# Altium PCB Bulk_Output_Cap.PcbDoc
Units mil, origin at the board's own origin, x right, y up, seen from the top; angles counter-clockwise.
Board outline 845 x 1377.95 mil, 6 copper layers (Top Layer, Layer 2, Layer 3, Layer 4, Layer 5, Bottom Layer), stack 43.736 mil thick; 2 components, 2 nets, 4 pads, 63 vias.
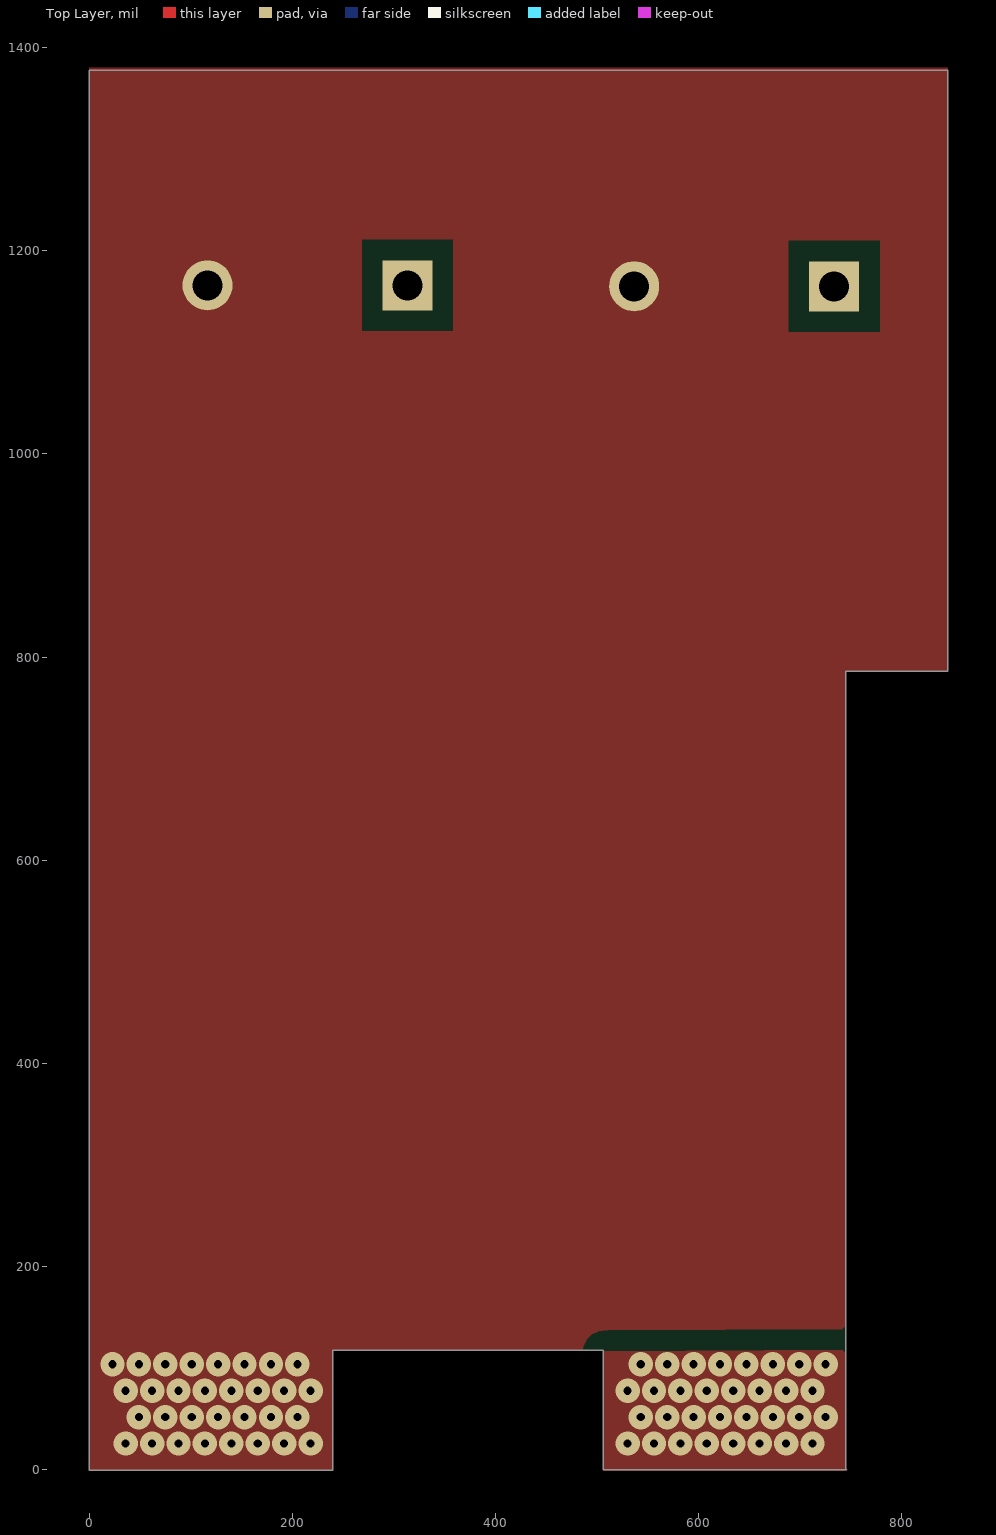
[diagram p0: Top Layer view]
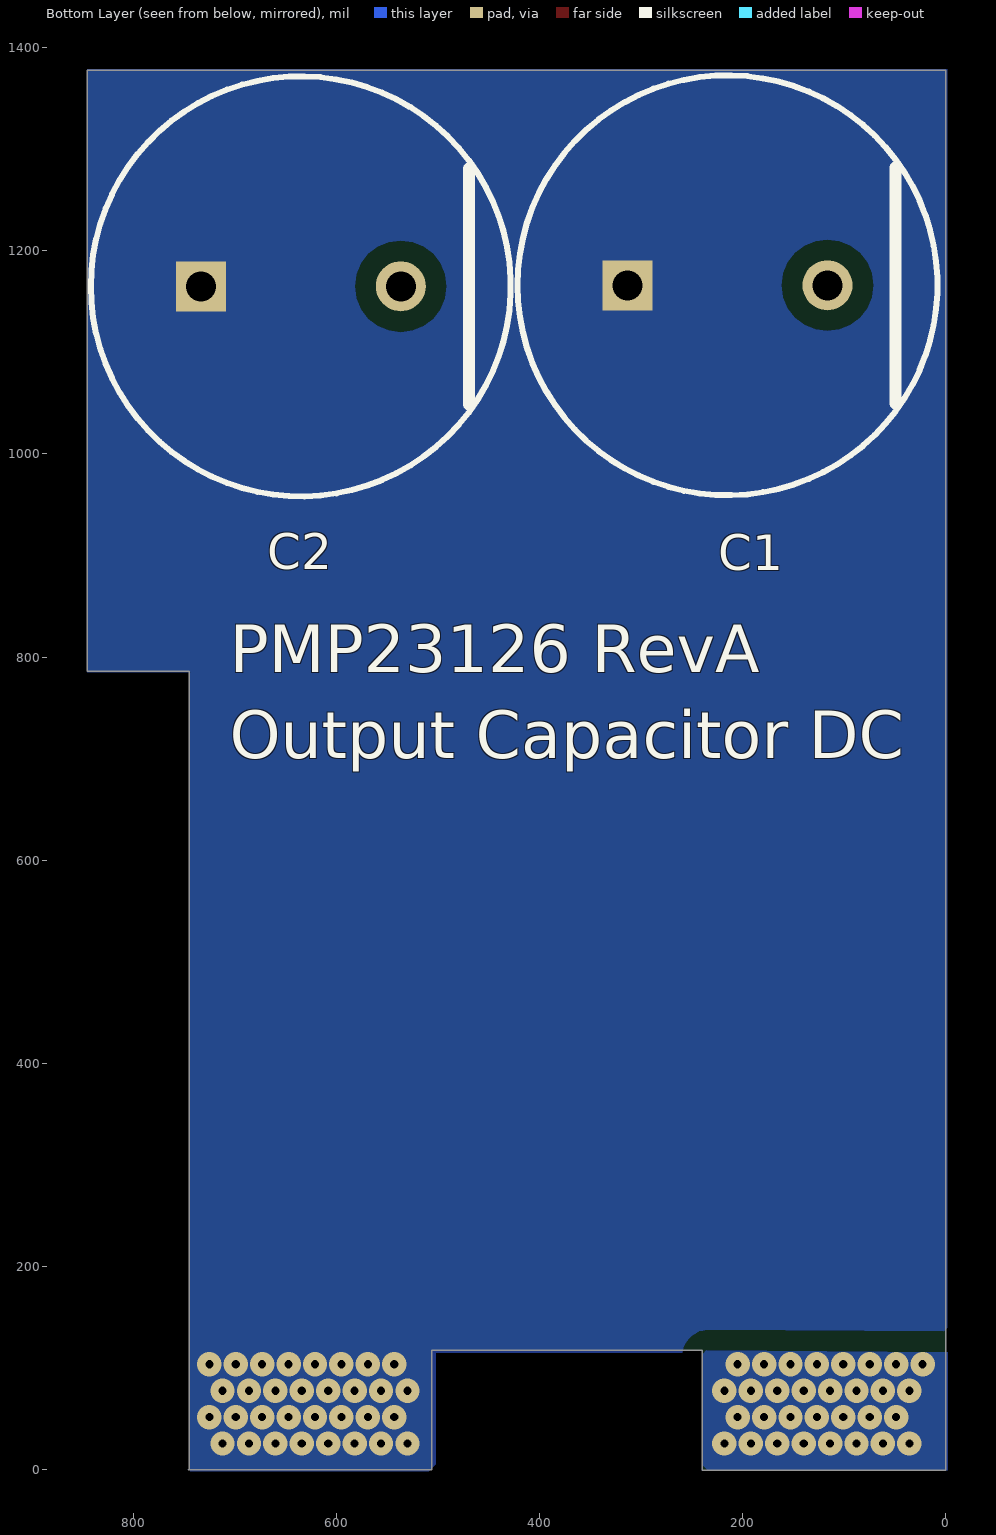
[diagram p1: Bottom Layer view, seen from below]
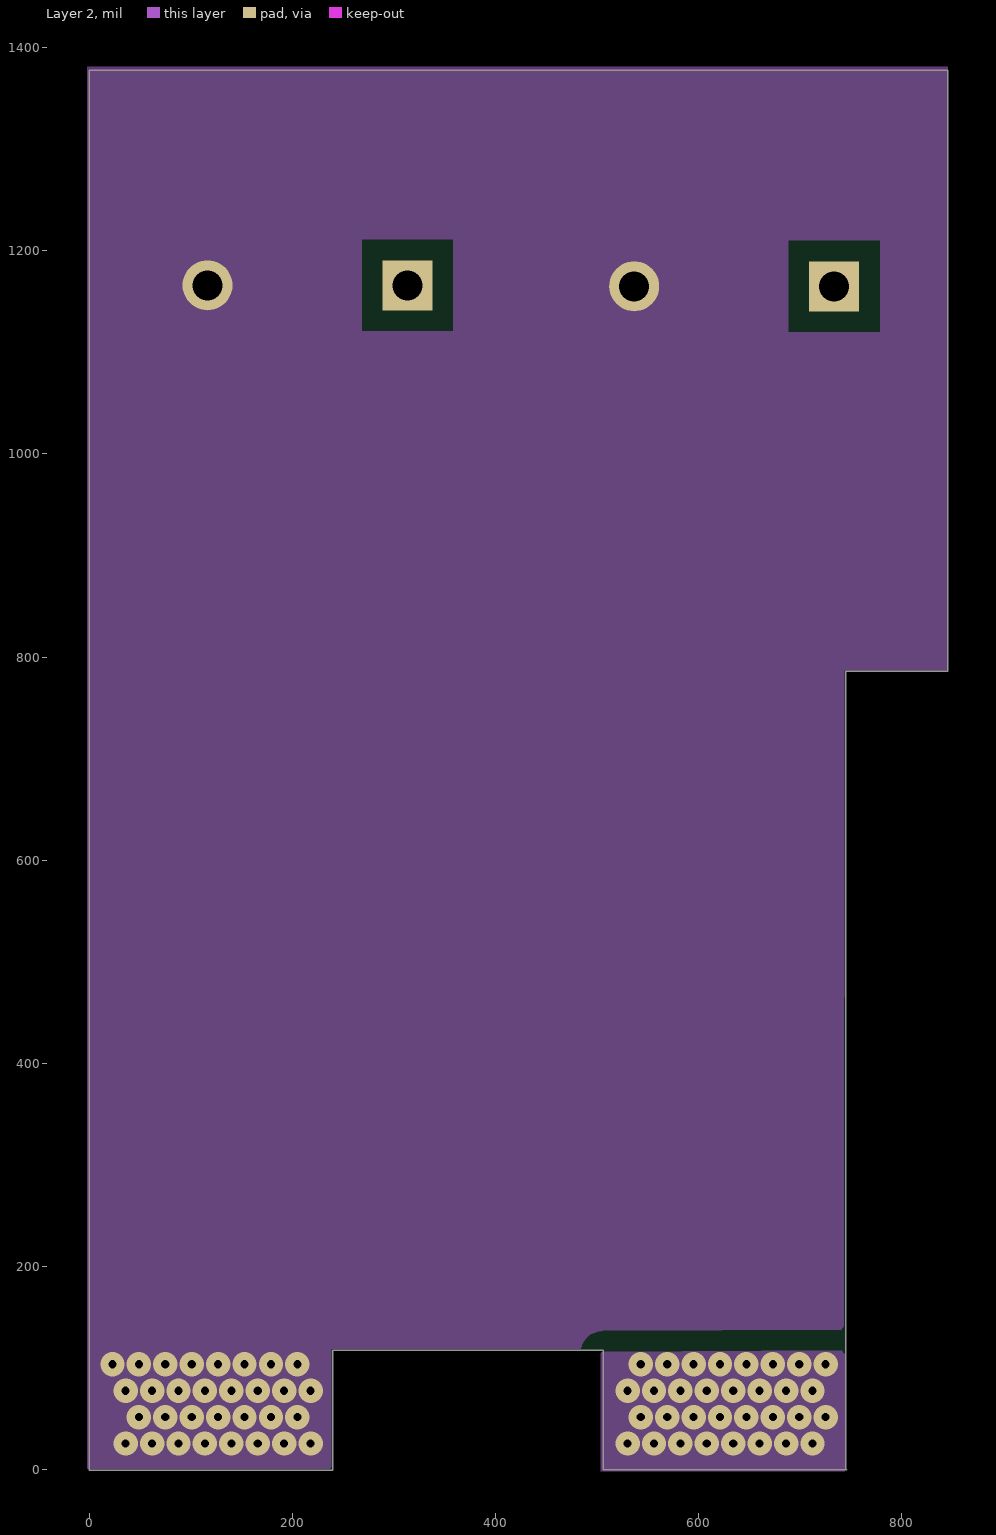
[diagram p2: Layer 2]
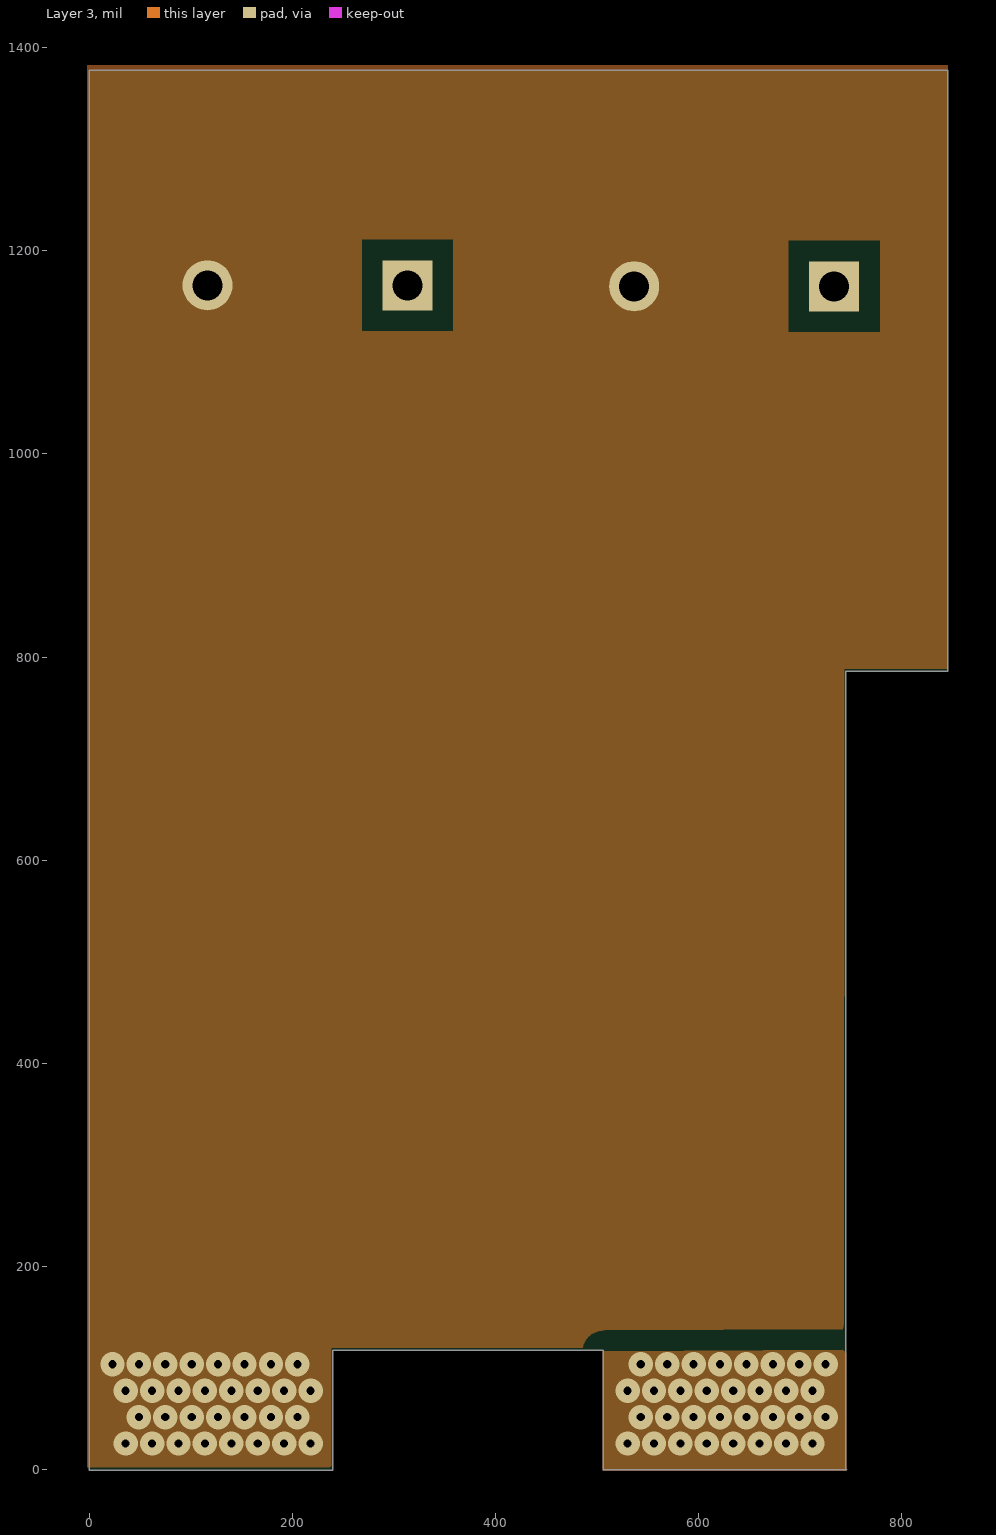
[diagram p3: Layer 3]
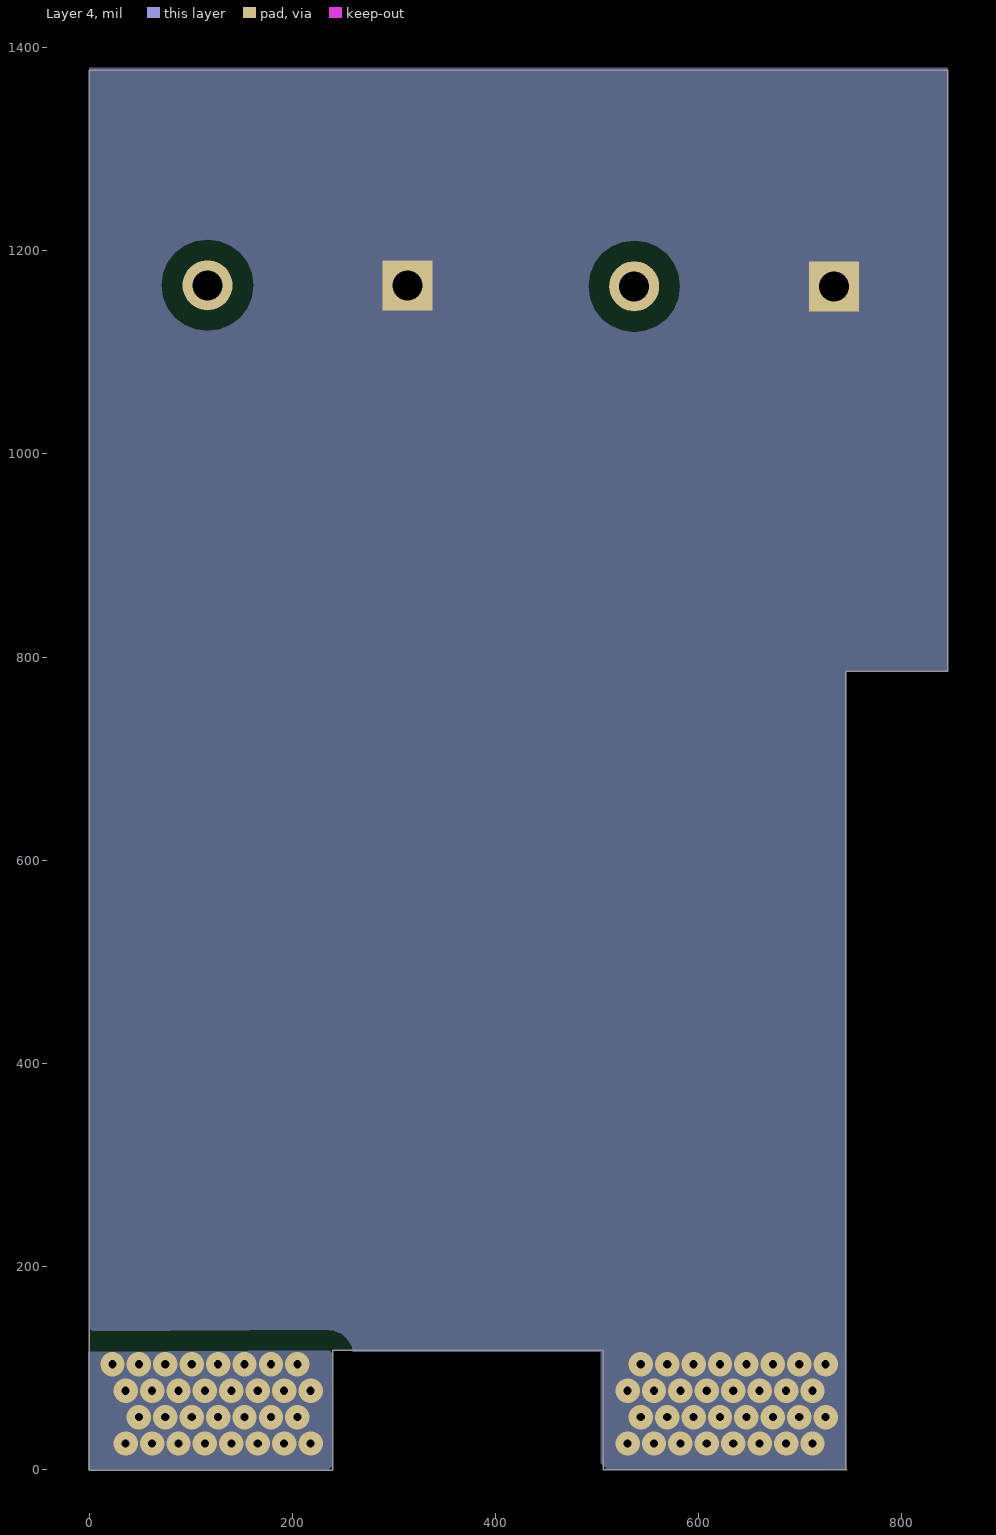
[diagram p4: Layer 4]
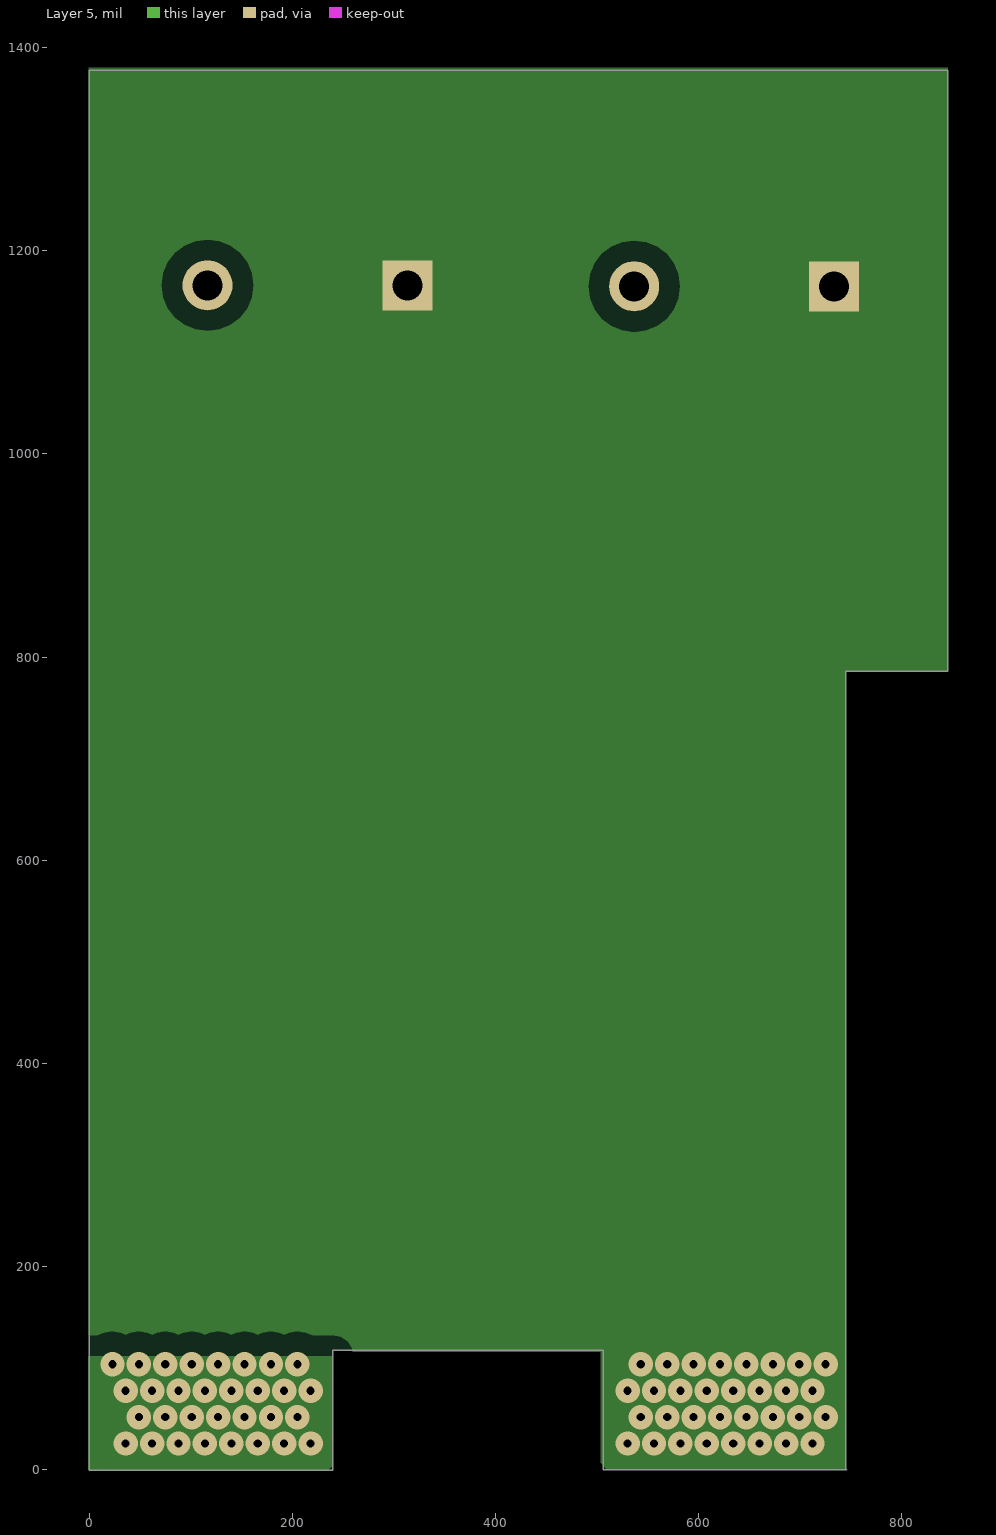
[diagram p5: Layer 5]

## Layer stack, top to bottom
Top Solder: solder mask 0.4, Solder Resist, Dk 3.5
Top Layer: signal copper 2.7559
Dielectric 1: prepreg 2.8, PP-006, Dk 4.1
Layer 2: signal copper 2.756
Dielectric 3: prepreg 2.8, PP-006, Dk 4.1
Layer 3: signal copper 2.7559
Dielectric1: core 16, Core-034, Dk 4.6
Layer 4: signal copper 2.7559
Dielectric 4: prepreg 2.8, PP-006, Dk 4.1
Layer 5: signal copper 2.756
Dielectric 2: prepreg 2.8, PP-006, Dk 4.1
Bottom Layer: signal copper 2.7559
Bottom Solder: solder mask 0.4, Solder Resist, Dk 3.5

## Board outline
0,-0.31 0,1377.64 845,1377.64 845,786 744.85,786 744.85,0.19 745.85,0.14 505.85,0.14 505.85,117.73 240,117.73 240,-0.31

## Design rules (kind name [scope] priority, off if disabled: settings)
AcuteAngle [All] p1: minimum=4.50000000000000E+0001 checktracksonly=FALSE
AssemblyTestPointUsage [All] p1: valid=2
Clearance Clearance_2 [InNetClass('HV') vs Not InNetClass('HV')] p1: gap=60 ignorepadtopadclearanceinfootprint=TRUE except(0: Arc-Hole Track-Hole SMDPad-Hole THPad-Hole Via-Hole Fill-Hole Poly-Hole Region-Hole Text-Hole)
Clearance Clearance_1 [InNetClass('MV') vs Not InNetClass('MV')] p2: gap=40 ignorepadtopadclearanceinfootprint=TRUE
Clearance Clearance_Keepouts [((IsTrack Or IsArc) And Not InPoly) And IsFree and IsKeepOut vs ((IsTrack Or IsArc) And Not InPoly) And IsFree and IsKeepOut] p3: gap=0 ignorepadtopadclearanceinfootprint=FALSE
Clearance Clearance_BoardEdge_MountingHoles [OnCopper and InComponentClass('Mounting Holes') vs IsKeepOut] p4: gap=40 ignorepadtopadclearanceinfootprint=FALSE except(0: Arc-Hole Track-Hole SMDPad-Hole THPad-Hole Via-Hole Fill-Hole Poly-Hole Region-Hole Text-Hole)
Clearance Clearance_BoardEdge_Poly [OnCopper and InPoly vs IsKeepOut] p5: gap=25 ignorepadtopadclearanceinfootprint=FALSE except(0: Arc-Hole Track-Hole SMDPad-Hole THPad-Hole Via-Hole Fill-Hole Poly-Hole Region-Hole Text-Hole)
Clearance Clearance_BoardEdge [OnCopper and Not InComponentClass('Logo') and not InComponentClass('FiducialMark') and not InRegion(1000,500,4000,800) and Not IsKeepout vs IsKeepOut] p6: gap=75 ignorepadtopadclearanceinfootprint=FALSE except(0: Arc-Hole Track-Hole SMDPad-Hole THPad-Hole Via-Hole Fill-Hole Poly-Hole Region-Hole Text-Hole)
Clearance Clearance_Poly [InPolygon] p7: gap=20 ignorepadtopadclearanceinfootprint=FALSE except(0: Arc-Hole Track-Hole SMDPad-Hole THPad-Hole Via-Hole Fill-Hole Poly-Hole Region-Hole Text-Hole)
Clearance [All] p8: gap=7.87 ignorepadtopadclearanceinfootprint=FALSE except(0: Arc-SMDPad Arc-Hole Track-Hole SMDPad-Hole THPad-Hole Via-Hole Fill-Hole Poly-Hole Region-Hole Text-Hole)
ComponentClearance ComponentClearance_MountingHoles_FiducialMarks [InComponentClass('Mounting Holes') vs InComponentClass('FiducialMark')] p1: gap=20 collisioncheckmode=3 verticalgap=7 showdistances=FALSE
ComponentClearance ComponentClearance_Shunt [InComponentClass('Header') vs InComponentClass('Shunt')] p2: gap=0 collisioncheckmode=3 verticalgap=0 showdistances=FALSE
ComponentClearance ComponentClearance_Logo [InComponentClass('Logo')] p3: gap=5 collisioncheckmode=3 verticalgap=10 showdistances=FALSE
ComponentClearance ComponentClearance_ScrewToNut [(HasFootprint('KEYSTONE_4824')) vs (HasFootprint('Keystone_1903C'))] p4: gap=0 collisioncheckmode=3 verticalgap=0 showdistances=FALSE
ComponentClearance ComponentClearance_MountingHoles [InComponentClass('Mounting Holes')] p5: gap=20 collisioncheckmode=3 verticalgap=7 showdistances=FALSE
ComponentClearance ComponentClearance_SmallPassives [HasFootprint('0201*') or HasFootprint('0402*') or HasFootprint('0508') or HasFootprint('0603*') or HasFootprint('0612') or HasFootprint('0805*') or HasFootprint('0815*') or HasFootprint('0830*') or HasFootprint('1206*') or HasFootprint('1210*') or HasFootprint('1808*') or HasFootprint('1812*') or HasFootprint('1825*') or HasFootprint('2010*') or HasFootprint('2220*') or HasFootprint('2225*') or HasFootprint('2512*') or HasFootprint('2728*') or HasFootprint('3518*') vs HasFootprint('0201*') or HasFootprint('0402*') or HasFootprint('0508') or HasFootprint('0603*') or HasFootprint('0612') or HasFootprint('0805*') or HasFootprint('0815*') or HasFootprint('0830*') or HasFootprint('1206*') or HasFootprint('1210*') or HasFootprint('1808*') or HasFootprint('1812*') or HasFootprint('1825*') or HasFootprint('2010*') or HasFootprint('2220*') or HasFootprint('2225*') or HasFootprint('2512*') or HasFootprint('2728*') or HasFootprint('3518*')] p6: gap=20 collisioncheckmode=3 verticalgap=20 showdistances=FALSE
ComponentClearance ComponentClearance_THtoSMT [IsThruComponent vs IsSMTComponent] p7: gap=10 collisioncheckmode=3 verticalgap=7 showdistances=FALSE
ComponentClearance ComponentClearance_THtoTH [IsThruComponent vs IsThruComponent] p8: gap=10 collisioncheckmode=3 verticalgap=7 showdistances=FALSE
ComponentClearance [All] p9: gap=10 collisioncheckmode=3 verticalgap=7 showdistances=FALSE
DiffPairsRouting [All] p1: maxlimit=100 minlimit=10 mostfreqgap=10 toplayer_minwidth=15 toplayer_maxwidth=15 toplayer_prefwidth=15 midlayer1_minwidth=15 midlayer1_maxwidth=15 midlayer1_prefwidth=15 midlayer2_minwidth=15 midlayer2_maxwidth=15 midlayer2_prefwidth=15 midlayer3_minwidth=15 midlayer3_maxwidth=15 midlayer3_prefwidth=15 midlayer4_minwidth=15 midlayer4_maxwidth=15 midlayer4_prefwidth=15 bottomlayer_minwidth=15 bottomlayer_maxwidth=15 bottomlayer_prefwidth=15 maxuncoupledlength=1000
FabricationTestPointUsage TestPointUsage [All] p1: valid=2 allowmultiple=FALSE
FabricationTestpoint Testpoint [All] p1: side=3 testpointundercomponent=TRUE minsize=40 maxsize=100 preferedsize=60 minholesize=0 maxholesize=40 preferedholesize=32 testpointgrid=1 allowsidetop=TRUE allowsidebottom=TRUE usegrid=TRUE gridtolerance=0.01
FanoutControl Fanout_LCC [IsLCC] p1: bgadir=Out bgaviamode=Centered fanoutstyle=Auto fanoutdirection=Alternating viagrid=1 // Fanout_LCC (Default Rule)
FanoutControl Fanout_BGA [IsBGA] p2: bgadir=Out bgaviamode=Centered fanoutstyle=Auto fanoutdirection=Alternating viagrid=1 // Fanout_BGA (Default Rule)
FanoutControl Fanout_Default [All] p4: bgadir=Out bgaviamode=Centered fanoutstyle=Auto fanoutdirection=Alternating viagrid=1 // Fanout_Default (Default Rule)
FanoutControl Fanout_Small [(CompPinCount < 5)] p5: bgadir=Out bgaviamode=Centered fanoutstyle=Auto fanoutdirection=OutThenIn viagrid=1 // Fanout_Small (Default Rule)
Height [All] p1: minheight=0 maxheight=3000 prefheight=500
HoleSize [All] p1: absolutevalues=TRUE maxlimit=501 minlimit=7 maxpercent=80.000 minpercent=20.000
MinimumAnnularRing MinimumAnnularRing_ThermalPadVias [IsVia and InAnyComponent] p1: minimumring=5.91
MinimumAnnularRing [All] p2: minimumring=5
MinimumSolderMaskSliver MinimumSolderMaskSliver_Logo [InComponentClass('Logo') vs InComponentClass('Logo')] p1: minsoldermaskwidth=0.7
MinimumSolderMaskSliver [All] p2: minsoldermaskwidth=3
PlaneConnect [All] p1: planeconnectstyle=Direct reliefexpansion=10 reliefentries=4 reliefconductorwidth=10 reliefairgap=10
PolygonConnect PolygonConnect_16 [All vs IsNamedPolygon('C106_2') Or  IsNamedPolygon('Vout') Or  IsNamedPolygon('IN+') Or  IsNamedPolygon('Q203_5') Or  IsNamedPolygon('IN+') Or  IsNamedPolygon('Q201_5') Or  IsNamedPolygon('C108_2') Or  IsNamedPolygon('SGND') Or  IsNamedPolygon('IN+') Or  IsNamedPolygon('SGND') Or  IsNamedPolygon('Q203_5') Or  IsNamedPolygon('IN+') Or  IsNamedPolygon('SGND') Or  IsNamedPolygon('GND') Or  IsNamedPolygon('C113_2') Or  IsNamedPolygon('C107_2') Or  IsNamedPolygon('C107_2') Or  IsNamedPolygon('Vout') Or  IsNamedPolygon('SIGNAL_LAYER_1_GND_P074') Or  IsNamedPolygon('HV') Or  IsNamedPolygon('C108_2') Or  IsNamedPolygon('C103_2') Or  IsNamedPolygon('Q201_5') Or  IsNamedPolygon('Vout') Or  IsNamedPolygon('C109_2') Or  IsNamedPolygon('Q201_5') Or  IsNamedPolygon('GND') Or  IsNamedPolygon('C107_2') Or  IsNamedPolygon('C102_1') Or  IsNamedPolygon('GND') Or  IsNamedPolygon('SGND') Or  IsNamedPolygon('HS') Or  IsNamedPolygon('Q203_5') Or  IsNamedPolygon('Q201_5') Or  IsNamedPolygon('Q203_5')] p1: connectstyle=Direct reliefconductorwidth=10 reliefentries=4 polygonreliefangle="90 Angle" airgapwidth=10
PolygonConnect PolygonConnect_15 [All vs IsNamedPolygon('C109_2') Or  IsNamedPolygon('C107_2') Or  IsNamedPolygon('HV') Or  IsNamedPolygon('Q203_5') Or  IsNamedPolygon('C107_2') Or  IsNamedPolygon('HS') Or  IsNamedPolygon('Q201_5') Or  IsNamedPolygon('Q203_5') Or  IsNamedPolygon('C106_2') Or  IsNamedPolygon('C108_2') Or  IsNamedPolygon('Vout') Or  IsNamedPolygon('Q203_5') Or  IsNamedPolygon('C108_2') Or  IsNamedPolygon('C113_2') Or  IsNamedPolygon('Q203_5') Or  IsNamedPolygon('Q201_5') Or  IsNamedPolygon('C107_2') Or  IsNamedPolygon('C102_1') Or  IsNamedPolygon('SGND') Or  IsNamedPolygon('GND') Or  IsNamedPolygon('SGND') Or  IsNamedPolygon('GND') Or  IsNamedPolygon('IN+') Or  IsNamedPolygon('IN+') Or  IsNamedPolygon('Q201_5') Or  IsNamedPolygon('Q201_5') Or  IsNamedPolygon('SGND') Or  IsNamedPolygon('SGND') Or  IsNamedPolygon('Vout') Or  IsNamedPolygon('Vout') Or  IsNamedPolygon('IN+') Or  IsNamedPolygon('GND') Or  IsNamedPolygon('IN+') Or  IsNamedPolygon('GND')] p2: connectstyle=Direct reliefconductorwidth=10 reliefentries=4 polygonreliefangle="90 Angle" airgapwidth=10
PolygonConnect PolygonConnect_14 [All vs IsNamedPolygon('C106_2') Or  IsNamedPolygon('C107_2') Or  IsNamedPolygon('C107_2') Or  IsNamedPolygon('C107_2') Or  IsNamedPolygon('C102_1') Or  IsNamedPolygon('Q203_5') Or  IsNamedPolygon('Vout') Or  IsNamedPolygon('Q203_5') Or  IsNamedPolygon('Q203_5') Or  IsNamedPolygon('Q201_5') Or  IsNamedPolygon('C108_2') Or  IsNamedPolygon('Q203_5') Or  IsNamedPolygon('HS') Or  IsNamedPolygon('HV') Or  IsNamedPolygon('C108_2') Or  IsNamedPolygon('Q201_5') Or  IsNamedPolygon('C109_2') Or  IsNamedPolygon('Q201_5') Or  IsNamedPolygon('Q201_5') Or  IsNamedPolygon('C113_2')] p3: connectstyle=Direct reliefconductorwidth=10 reliefentries=4 polygonreliefangle="90 Angle" airgapwidth=10
PolygonConnect PolygonConnect_13 [All vs IsNamedPolygon('C102_1') Or  IsNamedPolygon('HV') Or  IsNamedPolygon('C107_2') Or  IsNamedPolygon('C109_2') Or  IsNamedPolygon('C107_2') Or  IsNamedPolygon('C108_2') Or  IsNamedPolygon('C106_2') Or  IsNamedPolygon('C108_2') Or  IsNamedPolygon('C113_2') Or  IsNamedPolygon('C107_2')] p4: connectstyle=Direct reliefconductorwidth=10 reliefentries=4 polygonreliefangle="90 Angle" airgapwidth=10
PolygonConnect PolygonConnect_12 [All vs IsNamedPolygon('C107_2') Or  IsNamedPolygon('C113_2') Or  IsNamedPolygon('C106_2') Or  IsNamedPolygon('C107_2') Or  IsNamedPolygon('C107_2') Or  IsNamedPolygon('C102_1')] p5: connectstyle=Direct reliefconductorwidth=10 reliefentries=4 polygonreliefangle="90 Angle" airgapwidth=10
PolygonConnect PolygonConnect_11 [All vs IsNamedPolygon('C106_2') Or  IsNamedPolygon('C102_1') Or  IsNamedPolygon('C107_2') Or  IsNamedPolygon('C107_2') Or  IsNamedPolygon('C107_2')] p6: connectstyle=Direct reliefconductorwidth=10 reliefentries=4 polygonreliefangle="90 Angle" airgapwidth=10
PolygonConnect PolygonConnect_10 [All vs IsNamedPolygon('C106_2')] p7: connectstyle=Direct reliefconductorwidth=10 reliefentries=4 polygonreliefangle="90 Angle" airgapwidth=10
PolygonConnect PolygonConnect_9 [All vs IsNamedPolygon('C11_1') Or  IsNamedPolygon('Vin') Or  IsNamedPolygon('Vin') Or  IsNamedPolygon('5V') Or  IsNamedPolygon('D6_2') Or  IsNamedPolygon('Q3_3') Or  IsNamedPolygon('GND2') Or  IsNamedPolygon('GND2') Or  IsNamedPolygon('GND') Or  IsNamedPolygon('Q3_4') Or  IsNamedPolygon('12V5') Or  IsNamedPolygon('GND') Or  IsNamedPolygon('12V5') Or  IsNamedPolygon('D3_1')] p8: connectstyle=Direct reliefconductorwidth=10 reliefentries=4 polygonreliefangle="90 Angle" airgapwidth=10
PolygonConnect PolygonConnect_8 [All vs IsNamedPolygon('C11_1') Or  IsNamedPolygon('Vin') Or  IsNamedPolygon('12V5') Or  IsNamedPolygon('Q3_3') Or  IsNamedPolygon('GND2') Or  IsNamedPolygon('GND2') Or  IsNamedPolygon('5V') Or  IsNamedPolygon('Q3_4') Or  IsNamedPolygon('12V5')] p9: connectstyle=Direct reliefconductorwidth=10 reliefentries=4 polygonreliefangle="90 Angle" airgapwidth=10
PolygonConnect PolygonConnect_7 [All vs IsNamedPolygon('GND2') Or  IsNamedPolygon('GND2') Or  IsNamedPolygon('5V') Or  IsNamedPolygon('12V5') Or  IsNamedPolygon('12V5') Or  IsNamedPolygon('C11_1')] p10: connectstyle=Direct reliefconductorwidth=10 reliefentries=4 polygonreliefangle="90 Angle" airgapwidth=10
PolygonConnect PolygonConnect_6 [All vs IsNamedPolygon('GND2') Or  IsNamedPolygon('SGND') Or  IsNamedPolygon('GND1') Or  IsNamedPolygon('C901_1') Or  IsNamedPolygon('SGND') Or  IsNamedPolygon('GND2') Or  IsNamedPolygon('GND1')] p11: connectstyle=Direct reliefconductorwidth=10 reliefentries=4 polygonreliefangle="90 Angle" airgapwidth=10
PolygonConnect PolygonConnect_5 [All vs IsNamedPolygon('GND1') Or  IsNamedPolygon('GND1')] p12: connectstyle=Direct reliefconductorwidth=10 reliefentries=4 polygonreliefangle="90 Angle" airgapwidth=10
PolygonConnect PolygonConnect_4 [All vs IsNamedPolygon('C21_1') Or  IsNamedPolygon('C5_1') Or  IsNamedPolygon('C12_2') Or  IsNamedPolygon('C2_2') Or  IsNamedPolygon('C13_1') Or  IsNamedPolygon('C28_1') Or  IsNamedPolygon('C6_1') Or  IsNamedPolygon('GND') Or  IsNamedPolygon('GND2') Or  IsNamedPolygon('C14_1') Or  IsNamedPolygon('C13_1') Or  IsNamedPolygon('Q1_3') Or  IsNamedPolygon('C14_1') Or  IsNamedPolygon('C5_1') Or  IsNamedPolygon('GND2') Or  IsNamedPolygon('C28_1') Or  IsNamedPolygon('D5_2') Or  IsNamedPolygon('D6_2') Or  IsNamedPolygon('D2_1') Or  IsNamedPolygon('C12_2') Or  IsNamedPolygon('D2_1') Or  IsNamedPolygon('C4_1') Or  IsNamedPolygon('C4_1') Or  IsNamedPolygon('C2_2') Or  IsNamedPolygon('GND') Or  IsNamedPolygon('C33_1') Or  IsNamedPolygon('C9_1')] p13: connectstyle=Direct reliefconductorwidth=10 reliefentries=4 polygonreliefangle="90 Angle" airgapwidth=10
PolygonConnect PolygonConnect_3 [All vs IsNamedPolygon('C28_1') Or  IsNamedPolygon('C12_2') Or  IsNamedPolygon('C28_1') Or  IsNamedPolygon('C9_1') Or  IsNamedPolygon('D5_2') Or  IsNamedPolygon('C12_2') Or  IsNamedPolygon('C2_2') Or  IsNamedPolygon('C14_1') Or  IsNamedPolygon('C4_1') Or  IsNamedPolygon('C14_1') Or  IsNamedPolygon('D6_2') Or  IsNamedPolygon('GND2') Or  IsNamedPolygon('Q1_3') Or  IsNamedPolygon('C5_1') Or  IsNamedPolygon('D2_1') Or  IsNamedPolygon('C4_1') Or  IsNamedPolygon('C13_1') Or  IsNamedPolygon('C5_1') Or  IsNamedPolygon('C13_1') Or  IsNamedPolygon('C33_1') Or  IsNamedPolygon('D2_1') Or  IsNamedPolygon('GND') Or  IsNamedPolygon('GND') Or  IsNamedPolygon('GND2') Or  IsNamedPolygon('C2_2') Or  IsNamedPolygon('C6_1') Or  IsNamedPolygon('C21_1')] p14: connectstyle=Direct reliefconductorwidth=10 reliefentries=4 polygonreliefangle="90 Angle" airgapwidth=10
PolygonConnect PolygonConnect_2 [All vs IsNamedPolygon('C21_1') Or  IsNamedPolygon('C4_1') Or  IsNamedPolygon('D5_2') Or  IsNamedPolygon('C5_1') Or  IsNamedPolygon('C14_1') Or  IsNamedPolygon('C13_1') Or  IsNamedPolygon('C4_1') Or  IsNamedPolygon('C33_1') Or  IsNamedPolygon('C12_2') Or  IsNamedPolygon('D2_1') Or  IsNamedPolygon('C2_2') Or  IsNamedPolygon('C28_1') Or  IsNamedPolygon('C12_2') Or  IsNamedPolygon('D2_1') Or  IsNamedPolygon('C5_1') Or  IsNamedPolygon('Q1_3') Or  IsNamedPolygon('GND') Or  IsNamedPolygon('D6_2') Or  IsNamedPolygon('C6_1') Or  IsNamedPolygon('C2_2') Or  IsNamedPolygon('C14_1') Or  IsNamedPolygon('C28_1') Or  IsNamedPolygon('C13_1') Or  IsNamedPolygon('C9_1') Or  IsNamedPolygon('GND')] p15: connectstyle=Direct reliefconductorwidth=10 reliefentries=4 polygonreliefangle="90 Angle" airgapwidth=10
PolygonConnect PolygonConnect_1 [All vs IsNamedPolygon('C28_1') Or  IsNamedPolygon('D5_2') Or  IsNamedPolygon('C5_1') Or  IsNamedPolygon('C5_1') Or  IsNamedPolygon('D2_1') Or  IsNamedPolygon('C21_1') Or  IsNamedPolygon('C9_1') Or  IsNamedPolygon('C4_1') Or  IsNamedPolygon('C14_1') Or  IsNamedPolygon('C28_1') Or  IsNamedPolygon('C6_1') Or  IsNamedPolygon('C12_2') Or  IsNamedPolygon('C33_1') Or  IsNamedPolygon('C4_1') Or  IsNamedPolygon('C13_1') Or  IsNamedPolygon('C12_2') Or  IsNamedPolygon('D6_2') Or  IsNamedPolygon('C2_2') Or  IsNamedPolygon('C14_1') Or  IsNamedPolygon('D2_1') Or  IsNamedPolygon('C2_2') Or  IsNamedPolygon('C13_1')] p16: connectstyle=Direct reliefconductorwidth=10 reliefentries=4 polygonreliefangle="90 Angle" airgapwidth=10
PolygonConnect [All] p17: connectstyle=Direct reliefconductorwidth=10 reliefentries=4 polygonreliefangle="90 Angle" airgapwidth=10
RoutingVias ThermalPadVias [IsVia and not InNet('SGND')and not InNet('Vout')] p1: holewidth=7.87 width=19.68 viastyle="Through Hole" minholewidth=7.87 minwidth=19.68 maxholewidth=17 maxwidth=35
RoutingVias [IsVia and not InNet('SGND')and not InNet('Vout')] p2: holewidth=16 width=34 viastyle="Through Hole" minholewidth=7.87 minwidth=20 maxholewidth=40 maxwidth=65
SilkToBoardRegionClearance [Not ((IsComment or IsDesignator) And (Hide <> 'False')) and not InRegion(1000,500,4000,800)] p1:
SilkToSilkClearance SilkToSilkClearance_Pb-FreeLogo [(HasFootprint('Pb-Free_Overlay_Medium') OR HasFootprint('Pb-Free_Overlay_Small')) vs (HasFootprint('Pb-Free_Overlay_Medium') OR HasFootprint('Pb-Free_Overlay_Small'))] p1: silktosilkclearance=0
SilkToSilkClearance [All] p2: silktosilkclearance=3
SilkToSolderMaskClearance "Silk to Solder Mask Opening" [All] p1: minsilkscreentomaskgap=1 clearancetoexposedcopper=FALSE
SolderMaskExpansion [All] p1: expansion=1.97 istentingtop=FALSE
UnpouredPolygon [All] p1: allowunpoured=TRUE allowshelved=TRUE
Width [All] p1: maxlimit=100 minlimit=6 preferedwidth=10 checkconnectedcopper=TRUE
13 further rules are at their usual default settings.

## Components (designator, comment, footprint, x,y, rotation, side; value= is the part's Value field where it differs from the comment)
C1 "APSG160ELL222MJ20S" FP-APSG160ELL222MJ20S_RADIAL-MFG 215,1166 r0 bottom value=2.2mF
C2 "APSG160ELL222MJ20S" FP-APSG160ELL222MJ20S_RADIAL-MFG 635,1165 r0 bottom value=2.2mF

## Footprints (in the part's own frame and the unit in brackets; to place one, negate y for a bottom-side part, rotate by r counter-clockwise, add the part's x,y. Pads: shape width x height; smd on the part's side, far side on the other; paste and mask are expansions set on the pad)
FP-APSG160ELL222MJ20S_RADIAL-MFG [mm]
  round 1.25 hole 0.75 paste-1000 mask+0: 1(-2.5,0)
  rect 1.25x1.25 hole 0.75 paste-1000 mask+0: 2(2.5,0)
  silkscreen extent -5.25,-5.25 5.25,5.25, body extent -5,-5 5,5, height 21.5

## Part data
C1 C2: library part CMP-0094633-1, "2200 µF 16 V Aluminum - Polymer Capacitors Radial, Can 8mOhm 20000 Hrs @ 105°C", Digikey Part Number=565-4315-ND, Leakage Current=7040uA, Manufacturer="United Chemi-Con", Mouser Part Number=661-APSG160E222MJ20S, Operating Temperature Range="-55°C to +105°C", Tolerance_%=20%, ValueDisplayed=2200uF

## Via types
v1: diameter 24, hole 8, Top Layer to Bottom Layer, 63 vias

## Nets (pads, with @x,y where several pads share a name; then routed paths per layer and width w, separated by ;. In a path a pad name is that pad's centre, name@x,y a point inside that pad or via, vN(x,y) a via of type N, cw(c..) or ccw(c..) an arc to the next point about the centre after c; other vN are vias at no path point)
Iout_SNS: C1.2 C2.2
  other v1: 530,26 556,26 582,26 608,26 634,26 660,26 686,26 712,26 543,52 569,52 595,52 621,52 647,52 673,52 699,52 725,52 530,78 556,78 582,78 608,78 634,78 660,78 686,78 712,78 543,104 569,104 595,104 621,104 647,104 673,104 699,104 725,104
SGND: C1.1 C2.1
  other v1: 36,26 62,26 88,26 114,26 140,26 166,26 192,26 218,26 49,52 75,52 101,52 127,52 153,52 179,52 205,52 36,78 62,78 88,78 114,78 140,78 166,78 192,78 218,78 23,104 49,104 75,104 101,104 127,104 153,104 179,104 205,104

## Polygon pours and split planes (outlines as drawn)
Iout_SNS on Top Layer "TOP_LAYER_IOUT_SNS_P020" (solid, pour order 20): 505.85,116.98 505.85,-0.66 744.85,-0.66 744.85,118.24
SGND on Top Layer "TOP_LAYER_SGND_P045" (solid, remove dead copper, pour order 45): 0,1380 0,0 238.38,0 240,1.36 240,118.05 744.66,118.05 744.85,786 845,786 845,1380
SGND on Bottom Layer "BOTTOM_LAYER_SGND_P030" (solid, pour order 30): 239.26,117.62 239.26,0.62 238.51,-0.13 -1.65,-0.13 -1.65,115.97
Iout_SNS on Bottom Layer "BOTTOM_LAYER_IOUT_SNS_P050" (solid, remove dead copper, pour order 50): -1.46,1378.73 845,1378.73 845,785.24 743.91,785.24 743.39,784.73 743.76,784.36 743.76,-1.27 509.07,-1.27 502.3,5.5 502.3,115.11 2.81,115.11 -1.46,119.38
Iout_SNS on Layer 2 "LAYER_2_IOUT_SNS_P022" (solid, pour order 22): 503.76,116.38 503.76,-1.27 743.76,-1.27 743.76,117.64
SGND on Layer 2 "LAYER_2_SGND_P046" (solid, remove dead copper, pour order 46): -1.65,1381.14 -1.65,1.14 236.74,1.14 238.35,2.51 238.35,119.19 743.01,119.19 743.2,787.14 845,787.14 845,1381.14
Iout_SNS on Layer 3 "LAYER_3_IOUT_SNS_P023" (solid, pour order 23): 505.35,116.98 505.35,-0.67 745.35,-0.67 745.35,118.24
SGND on Layer 3 "LAYER_3_SGND_P047" (solid, remove dead copper, pour order 47): -1.65,1382.42 -1.65,2.42 236.74,2.42 238.35,3.78 238.35,120.46 743.01,120.46 743.2,788.42 845,788.42 845,1382.42
SGND on Layer 4 "LAYER_4_SGND_P028" (solid, pour order 28): 240,117.73 240,0.73 239.26,-0.01 -0.91,-0.01 -0.91,116.09
Iout_SNS on Layer 4 "LAYER_4_IOUT_SNS_P048" (solid, remove dead copper, pour order 48): 0,1380 845,1380 845,786.52 745.37,786.52 744.85,786 745.22,785.63 745.22,0 510.53,0 503.76,6.77 503.76,116.38 4.27,116.38 0,120.65
no net on Top Solder "TOP_LAYER_NONET_P-001" (solid): 0,117.73 0,-0.31 239.27,-0.31 240,0.42 240,117.73
no net on Top Solder "TOP_LAYER_NONET_P-001" (solid): 505.35,117.61 505.35,-0.44 744.62,-0.44 745.35,0.29 745.35,117.61
SGND on Layer 5 "LAYER_5_SGND_P029" (solid, pour order 29): 240,117.73 240,0.73 239.26,-0.01 -0.91,-0.01 -0.91,116.09
Iout_SNS on Layer 5 "LAYER_5_IOUT_SNS_P049" (solid, remove dead copper, pour order 49): -0.37,1380.19 845,1380.19 845,786.7 745,786.7 744.48,786.19 744.85,785.82 744.85,0.19 510.16,0.19 503.39,6.96 503.39,116.57 3.91,116.57 -0.37,120.84
no net on Bottom Solder "TOP_LAYER_NONET_P-001" (solid): 0,118.05 0,0 239.27,0 240,0.73 240,118.05
no net on Bottom Solder "TOP_LAYER_NONET_P-001" (solid): 505.35,117.61 505.35,-0.44 744.62,-0.44 745.35,0.29 745.35,117.61

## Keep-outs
Keep-Out Layer:
  text ".Layer_Name" at 577,-858.49 h60

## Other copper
Top Layer:
  text ".Layer_Name" at 577,-858.49 h60
Bottom Layer:
  text ".Layer_Name" at 577,-858.49 h60

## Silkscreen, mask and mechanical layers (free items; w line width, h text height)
Top Overlay:
  text ".Layer_Name" at 577,-858.49 h60
Bottom Overlay:
  text "PMP23126 RevA" at 705,770 h80
  text "Output Capacitor DC" at 705,685 h80
  text ".Layer_Name" at 577,-858.49 h60
Top Paste:
  text ".Layer_Name" at 577,-858.49 h60
Bottom Paste:
  text ".Layer_Name" at 577,-858.49 h60
Top Solder:
  text ".Layer_Name" at 577,-858.49 h60
  text ".Layer_Name" at 577,-858.49 h60
Bottom Solder:
  text ".Layer_Name" at 577,-858.49 h60
Drill Guide:
  text ".Layer_Name" at 577,-858.49 h60
M1 Board Outline:
  lines w10: 240,-0.38 240,117.73 505.85,117.73 505.85,-0.38 ; 240,-0.31 0,-0.31 0,1377.64 845,1377.64 845,786 744.85,786 744.85,0.19 ; 505.85,0.14 745.85,0.14
  text ".Layer_Name" at 577,-858.49 h60
M2 Board Dimensions:
  rectangle: 125,-400 500,-275
  rectangle: 0,-275 125,-150
  lines w7: 0,-275 1000,-275 ; 125,-400 125,-150 ; 250,-400 250,-150 ; 500,-400 500,-150 ; 750,-400 750,-150 ; 0,-400 0,-150 1000,-150 1000,-400 0,-400
  text ".Layer_Name" at 577,-858.49 h60
M3 3D STEP Top:
  text ".Layer_Name" at 577,-858.49 h60
M4 3D STEP Bottom:
  text ".Layer_Name" at 577,-858.49 h60
M5 Assembly Top:
  lines w10: -292,-930.17 6308,-930.17 ; -292,-726.83 6310,-726.83 ; -292,-523.5 -292,-1133.5 3713,-1133.5 6310,-1133.5 6310,-523.5 -291.5,-523.5 -291.5,-1133.5 1284,-1133.5 ; 2173,-1133.5 2173,-523.5 ; 3440,-726.83 3440,-523.5 ; 4280,-726.83 4280,-523.5 ; 4902,-1140 4902,-937.17
  text "COMPONENTS MARKED 'DNP' SHOULD NOT BE POPULATED." at 1153.5,-318.5 h60
  text "ASSEMBLY VARIANT:" at 1153,-434 h60
  text ".VariantName" at 2189,-434 h60
  text "PCB VIEWED FROM TOP SIDE" at -228.5,-655.67 h60
  text "BOARD #:" at 2248,-655.67 h60
  text ".PRJ_Number" at 2793.5,-655.67 h60
  text "REV:" at 3638,-655.67 h60
  text ".PCB_Rev" at 3929.5,-655.67 h60
  text "SVN REV:" at 4476,-655.67 h60
  text ".VersionControl_RevNumber" at 4982,-655.67 h60
  text "TID #:" at 2248,-859 h60
  text ".TID" at 2793.5,-859 h60
  text "PLOT NAME =" at -228.5,-1064.34 h60
  text ".plot_File_Name" at 577,-1064.34 h60
  text "GENERATED    :" at 2250,-1064.34 h60
  text ".Print_Date" at 3119.5,-1064.34 h60
  text ".Print_Time" at 3848.5,-1064.34 h60
  text "TEXAS INSTRUMENTS" at 5113,-1064.34 h60
M6 Assembly Bottom:
  lines w10: -292.5,-727.33 6309.5,-727.33 ; -290.5,-930.67 6309.5,-930.67 ; 1115.5,-1140.5 1115.5,-937.67 ; 1737.5,-727.33 1737.5,-524 ; 2577.5,-727.33 2577.5,-524 ; 3844.5,-1134 3844.5,-524 ; 4733.5,-1134 6309,-1134 6309,-524 -292.5,-524 -292.5,-1134 2304.5,-1134 6309.5,-1134 6309.5,-524
  text "COMPONENTS MARKED 'DNP' SHOULD NOT BE POPULATED." at 6102,-318 h60
  text ".VariantName" at 5058,-434 h60
  text "ASSEMBLY VARIANT:" at 6097,-434 h60
  text ".VersionControl_RevNumber" at 1035.5,-656.17 h60
  text "SVN REV:" at 1541.5,-656.17 h60
  text ".PCB_Rev" at 2088,-656.17 h60
  text "REV:" at 2379.5,-656.17 h60
  text ".PRJ_Number" at 3224,-656.17 h60
  text "BOARD #:" at 3769.5,-656.17 h60
  text "PCB VIEWED FROM BOTTOM SIDE" at 6246,-656.17 h60
  text ".TID" at 3224,-859.5 h60
  text "TID #:" at 3769.5,-859.5 h60
  text "TEXAS INSTRUMENTS" at 904.5,-1064.84 h60
  text ".Print_Time" at 2169,-1064.84 h60
  text ".Print_Date" at 2898,-1064.84 h60
  text "GENERATED    :" at 3767.5,-1064.84 h60
  text ".plot_File_Name" at 5440.5,-1064.84 h60
  text "PLOT NAME =" at 6246,-1064.84 h60
M9 Title Sheet:
  drawing of 57 lines, arcs and shapes, not listed
  text "1" at 739.84,8036.5 h70
  text "2" at 3235.5,8036.5 h70
  text "3" at 5724.84,8036.5 h70
  text "4" at 8231.51,8036.5 h70
  text "5" at 10730.5,8036.5 h70
  text "6" at 13235.5,8036.5 h70
  text "A" at -416.5,6893.5 h70
  text "A" at 14383.5,6893.5 h70
  text "B" at -416.5,4513.5 h70
  text "B" at 14383.5,4513.5 h70
  text "C" at -416.5,2138.5 h70
  text "C" at 14383.5,2138.5 h70
  text "PROJECT TITLE:" at 11343.5,277.5 h45
  text ".PRJ_Title" at 11393.5,144.17 h70
  text "DESIGNED FOR:" at 11343.5,-23.5 h45
  text ".PRJ_Customer" at 11393.5,-163.5 h70
  text "D" at -416.5,-231.5 h70
  text "D" at 14383.5,-231.5 h70
  text "FILE NAME:" at 11343.5,-323.5 h45
  text ".PCB_File_Name_No_Path" at 11393.5,-443.5 h70
  text "Texas Instruments (TI) and/or its licensors do not warrant the accuracy or completeness of this specification" at 6374,-605.34 h45
  text "ENGINEER:" at 11343.5,-613.5 h45
  text "LAYOUT BY:" at 12848.5,-613.5 h45
  text "or any information contained therein. TI and/or its licensors do not warrant that this design will meet" at 6329.01,-718 h45
  text ".PRJ_Engineer" at 11393.5,-768.49 h70
  text ".PCB_Layout" at 12899,-768.49 h70
  text "the specifications, will be suitable for your application or fit for any particular purpose, or will operate in" at 6329.01,-830.67 h45
  text ".Layer_Name" at 577,-858.49 h60
  text "ALTIUM DESIGNER VERSION:" at 12848.5,-923.5 h45
  text "an implementation. TI and/or its licensors do not warrant that the design is production worthy. You should" at 6329.01,-943.33 h45
  text "completely validate and test your design implementation to confirm the system functionality for your application." at 6374,-1056 h45
  text ".print_Scale" at 11393.5,-1056.83 h70
  text ".Application_BuildNumber" at 12899,-1056.83 h70
  text "1" at 739.84,-1263.5 h70
  text "2" at 3235.5,-1263.5 h70
  text "3" at 5724.84,-1263.5 h70
  text "4" at 8231.51,-1263.5 h70
  text "5" at 10730.5,-1263.5 h70
  text "6" at 13235.5,-1263.5 h70
M10 Fab Notes:
  drawing of 189 lines, arcs and shapes, not listed
  text "DESIGN INFORMATION" at 12382.02,6356.17 h60
  text "MIN. TRACK WIDTH:" at 11737.46,6224.05 h60
  text "8" at 12833.7,6224.05 h60
  text "MIL" at 12988.46,6224.05 h60
  text "7.874" at 12667.32,6102.36 h60
  text "MIN. CLEARANCE:" at 11737.46,6099.92 h60
  text "MIL" at 12988.46,6099.92 h60
  text "MIN. VIA PAD SIZE:" at 11737.46,5975.8 h60
  text "24" at 12803.71,5975.8 h60
  text "MIL" at 12988.46,5975.8 h60
  text "0.05mm (2MIL)" at 12432.46,5845.9 h60
  text "MINIMUM ANNULAR RING" at 11408.23,5837.67 h60
  text "EXTERNAL" at 13140.46,5837.67 h60
  text "PER" at 11608.23,5727.55 h60
  text "IPC-D-275 CLASS 2 LEVEL C" at 11828.23,5727.54 h60
  text "MIL, HOLES" at 13316.46,5627.07 h60
  text "+/-" at 12924,5618.48 h60
  text "+/-" at 13778,5618.48 h60
  text "REGISTRATION TOLERANCES:" at 11408.23,5617.42 h60
  text "METAL" at 12608,5617.42 h60
  text "5" at 13184.2,5617.42 h60
  text "3" at 14017.2,5617.42 h60
  text "MIL" at 14133.46,5617.42 h60
  text "HOLE SIZE TOLERANCE (UNLESS OTHERWISE SPECIFIED):" at 11408.23,5519.1 h60
  text "+/-" at 13778,5516.23 h60
  text "3" at 14017.2,5515.17 h60
  text "MIL" at 14133.46,5515.17 h60
  text "MATERIAL:" at 11333.46,5377.52 h60
  text "FR-4 High Tg" at 12319.9,5249 h60
  text "X" at 12175.46,5241.01 h60
  text "FR-408" at 11754.46,5236.49 h60
  text "OTHER" at 13242.46,5236.49 h60
  text "62 MIL (1.6mm) +/-10%" at 12074.56,5093.46 h60
  text "X" at 11954.46,5091.01 h60
  text "THICKNESS:" at 11408.23,5085.24 h60
  text "OTHER" at 13359.46,5085.24 h60
  text "TOLERANCE:" at 11408.23,4946.92 h60
  text "X" at 12256.46,4946.92 h60
  text "ANSI IPC-6012 TYPE 3 CLASS 2" at 12434.48,4946.92 h60
  text "OTHER +/-" at 12434.46,4802.73 h60
  text "BOW & TWIST:" at 11408.23,4657.54 h60
  text "X" at 12256.46,4657.54 h60
  text "ANSI IPC-6012 TYPE 3 CLASS 2" at 12434.48,4657.54 h60
  text "OTHER +/-" at 12434.46,4510.85 h60
  text "DRILLING:" at 11333.46,4380.23 h60
  text "NC_DRILL FILES" at 13094.46,4275.04 h60
  text "REFERENCE:" at 11408.23,4271.1 h60
  text "X" at 12065.46,4271.01 h60
  text "AS SHOWN" at 12243.46,4271.1 h60
  text "X" at 12966.46,4271.1 h60
  text "OTHER" at 13392.46,4128.85 h60
  text "PTH COPPER THICKNESS:" at 11407.91,4125.32 h60
  text "X" at 12547.14,4125.32 h60
  text "20-30 um" at 12675.14,4125.32 h60
  text "BOARD FINISH:" at 11333.46,3977.73 h60
  text "SILKSCREEN:" at 11488.68,3867.6 h60
  text "X" at 12446.46,3867.6 h60
  text "TOP" at 12563.46,3867.6 h60
  text "X" at 12956.46,3867.6 h60
  text "BOTTOM" at 13074.46,3867.6 h60
  text "SILKSCREEN COLOR:" at 11488.68,3712.41 h60
  text "X" at 12445.46,3712.41 h60
  text "WHITE" at 12563.46,3712.41 h60
  text "OTHER" at 13074.46,3712.41 h60
  text "X" at 12576.46,3568.96 h60
  text "GREEN" at 12694.46,3568.96 h60
  text "OTHER" at 13312.46,3568.96 h60
  text "SOLDER RESIST COLOR:" at 11488.68,3562.1 h60
  text "X" at 12576.46,3414.71 h60
  text "MATTE" at 12694.46,3414.71 h60
  text "SEMI-GLOSS" at 13312,3414.07 h60
  text "IMMERSION GOLD (ENIG)" at 12394.46,3241.94 h60
  text "ENEPIG" at 13732,3234.72 h60
  text "SURFACE FINISH:" at 11333.46,3233.72 h60
  text "X" at 12216.46,3233.72 h60
  text "IMM. TIN/SILVER OR EQUIV" at 11663,3096.4 h60
  text "OTHER" at 13094.46,3092.47 h60
  text "ARRAY/PANEL:" at 11333.46,2937.09 h60
  text "CUT AND TRIM PER M1 BOARD OUTLINE" at 12394.46,2928.87 h60
  text "N.C. ROUTE" at 12394.46,2792.9 h60
  text "X" at 13082.46,2792.9 h60
  text "V. SCORE" at 13260.46,2792.9 h60
  text "CERTIFICATION:" at 11333.46,2663.77 h60
  text "MATERIALS AND WORKMANSHIP FOR ALL PCBS" at 12058.46,2663.77 h60
  text "TO MEET OR EXCEED THE REQUIREMENTS OF:" at 12058.46,2569.71 h60
  text "X" at 11695.97,2441.08 h60
  text "ANSI IPC-A-600F CLASS ->" at 11823.96,2441.08 h60
  text "X" at 13471.97,2441.08 h60
  text "2" at 13581.96,2441.08 h60
  text "1" at 13266.96,2439.58 h60
  text "3" at 13935.96,2439.58 h60
  text "X" at 12507.97,2293.39 h60
  text "RoHS" at 12635.96,2293.39 h60
  text "OTHER" at 13280.36,2293.39 h60
  text "PER ORDER" at 13677.42,2293.39 h60
  text "ALL BOARDS MUST MEET OR EXCEED UL94-V0 REQUIREMENTS." at 11361,2139.57 h60
  text "PCB MUST BEAR THE UL94V-0 UL REGISTERED MATERIAL ID NUMBER" at 11361,2023.5 h60
  text "ADDITIONAL REQUIREMENTS:" at 11333.46,1854.08 h60
  text "MICROSECTION:" at 11408.23,1746.95 h60
  text "YES" at 12313.96,1746.95 h60
  text "REQUIRED" at 13175.46,1602.62 h60
  text "BARE BOARD ELEC. TEST:" at 11408.23,1599.76 h60
  text "NONE" at 12713.96,1599.76 h60
  text "X" at 13057.46,1599.76 h60
  text "PER ORDER" at 13767.46,1599.76 h60
  text "XX MIL VIAS REQUIRE NON-CONDUCTIVE FILL AND PLANARIZE" at 11576.38,1394.82 h59
  text "XX MIL VIAS REQUIRE CONDUCTIVE FILL AND PLANARIZE" at 11584.38,1290.84 h60
  text "OUTER XX MIL TRACES REQUIRE 50 OHM SINGLE-ENDED IMPEDANCE" at 11583.39,1127.46 h58
  text "LAYER 2 & 3 (INNER LAYERS) XX MIL WIDE, XX MIL SPACE / TRACES REQUIRE 100 OHM DIFFERENTIAL IMPEDANCE" at 11575.39,891.74 h60
  text ".Layer_Name" at 577,-858.49 h60
M11 Gerber Information:
  lines w10: -292,-930.17 6308,-930.17 ; -292,-726.83 6310,-726.83 ; -292,-523.5 -292,-1133.5 3713,-1133.5 6310,-1133.5 6310,-523.5 -291.5,-523.5 -291.5,-1133.5 1284,-1133.5 ; 2173,-1133.5 2173,-523.5 ; 3440,-726.83 3440,-523.5 ; 4280,-726.83 4280,-523.5 ; 4902,-1140 4902,-937.17
  text "ALL ARTWORK VIEWED FROM TOP SIDE" at -228.5,-655.67 h60
  text "BOARD #:" at 2248,-655.67 h60
  text ".PRJ_Number" at 2793.5,-655.67 h60
  text "REV:" at 3638,-655.67 h60
  text ".PCB_Rev" at 3929.5,-655.67 h60
  text "SVN REV:" at 4476,-655.67 h60
  text ".VersionControl_RevNumber" at 4982,-655.67 h60
  text "LAYER NAME =" at -228.5,-858.49 h60
  text "TID #:" at 2248,-859 h60
  text ".TID" at 2793.5,-859 h60
  text "PLOT NAME =" at -228.5,-1064.34 h60
  text ".plot_File_Name" at 577,-1064.34 h60
  text "GENERATED    :" at 2250,-1064.34 h60
  text ".Print_Date" at 3119.5,-1064.34 h60
  text ".Print_Time" at 3848.5,-1064.34 h60
  text "TEXAS INSTRUMENTS" at 5113,-1064.34 h60
M12 Stackup:
  drawing of 399 lines, arcs and shapes, not listed
  text "Layer" at 4285.19,5585.01 h60
  text "Name" at 4695.11,5585.01 h60
  text "Material" at 5624.85,5585.01 h60
  text "Thickness" at 6484.62,5585.01 h60
  text "Constant" at 7134.45,5585.01 h60
  text "Board Layer Stack" at 7704.31,5585.01 h60
  text "Top Overlay" at 4695.11,5465.01 h60
  text "Top Solder" at 4695.11,5345.01 h60
  text "Solder Resist" at 5624.85,5345.01 h60
  text "0.40mil" at 6484.62,5345.01 h60
  text "3.5" at 7134.45,5345.01 h60
  text "1" at 4285.19,5225.01 h60
  text "Top Layer" at 4695.11,5225.01 h60
  text "2.76mil" at 6484.62,5225.01 h60
  text "Dielectric 1" at 4695.11,5105.01 h60
  text "PP-006" at 5624.85,5105.01 h60
  text "2.80mil" at 6484.62,5105.01 h60
  text "4.1" at 7134.45,5105.01 h60
  text "2" at 4285.19,4985.01 h60
  text "Layer 2" at 4695.11,4985.01 h60
  text "2.76mil" at 6484.62,4985.01 h60
  text "Dielectric 3" at 4695.11,4865.01 h60
  text "PP-006" at 5624.85,4865.01 h60
  text "2.80mil" at 6484.62,4865.01 h60
  text "4.1" at 7134.45,4865.01 h60
  text "3" at 4285.19,4745.01 h60
  text "Layer 3" at 4695.11,4745.01 h60
  text "2.76mil" at 6484.62,4745.01 h60
  text "Dielectric1" at 4695.11,4625.01 h60
  text "Core-034" at 5624.85,4625.01 h60
  text "16.00mil" at 6484.62,4625.01 h60
  text "4.6" at 7134.45,4625.01 h60
  text "4" at 4285.19,4505.01 h60
  text "Layer 4" at 4695.11,4505.01 h60
  text "2.76mil" at 6484.62,4505.01 h60
  text "Dielectric 4" at 4695.11,4385.01 h60
  text "PP-006" at 5624.85,4385.01 h60
  text "2.80mil" at 6484.62,4385.01 h60
  text "4.1" at 7134.45,4385.01 h60
  text "5" at 4285.19,4265.01 h60
  text "Layer 5" at 4695.11,4265.01 h60
  text "2.76mil" at 6484.62,4265.01 h60
  text "Dielectric 2" at 4695.11,4145.01 h60
  text "PP-006" at 5624.85,4145.01 h60
  text "2.80mil" at 6484.62,4145.01 h60
  text "4.1" at 7134.45,4145.01 h60
  text "6" at 4285.19,4025.01 h60
  text "Bottom Layer" at 4695.11,4025.01 h60
  text "2.76mil" at 6484.62,4025.01 h60
  text "Bottom Solder" at 4695.11,3905.01 h60
  text "Solder Resist" at 5624.85,3905.01 h60
  text "0.40mil" at 6484.62,3905.01 h60
  text "3.5" at 7134.45,3905.01 h60
  text "Bottom Overlay" at 4695.11,3785.01 h60
  text ".Layer_Name" at 577,-858.49 h60
M13 Component Bodies Top:
  text ".Layer_Name" at 577,-858.49 h60
M14 Component Bodies Bottom:
  text ".Layer_Name" at 577,-858.49 h60
M15 Courtyards Top:
  text ".Layer_Name" at 577,-858.49 h60
M16 Courtyards Bottom:
  text ".Layer_Name" at 577,-858.49 h60
Drill Drawing:
  circle w10: c5058.72,2965.24 r27.63
  lines w10: 5031.09,3075.75 5044.9,3075.75 5058.72,3061.94 5072.53,3075.75 5086.34,3075.75 5072.53,3089.56 5086.34,3103.38 5072.53,3103.38 5058.72,3117.19 5044.9,3103.38 5031.09,3103.38 5044.9,3089.56 5031.09,3075.75
  lines w12: 4981,2900.32 8078.37,2900.32 ; 4981,3148.96 8078.37,3148.96 ; 5318.86,2776 5318.86,3273.28 ; 5590.37,2776 5590.37,3273.28 ; 6153.3,2776 6153.3,3273.28 ; 6412.44,2776 6412.44,3273.28 ; 6787.6,2776 6787.6,3273.28 ; 7511.93,2776 7511.93,3273.28 ; 4981,2776 8078.37,2776 8078.37,3273.28 4981,3273.28 4981,2776
  text "Symbol" at 5055.59,3186.26 h72
  text "Count" at 5356.16,3186.26 h72
  text "Hole Size" at 5627.66,3186.26 h72
  text "Plated" at 6190.6,3186.26 h72
  text "Hole Type" at 6449.74,3186.26 h72
  text "Drill Layer Pair" at 6824.9,3186.26 h72
  text "Hole Tolerance" at 7549.23,3186.26 h72
  text "63" at 5356.16,3061.94 h60
  text "8.00mil (0.203mm)" at 5627.66,3061.94 h60
  text "PTH" at 6190.6,3061.94 h60
  text "Round" at 6449.74,3061.94 h60
  text "Top Layer - Bottom Layer" at 6824.9,3061.94 h60
  text "4" at 5356.16,2937.62 h60
  text "29.53mil (0.750mm)" at 5627.66,2937.62 h60
  text "PTH" at 6190.6,2937.62 h60
  text "Round" at 6449.74,2937.62 h60
  text "Top Layer - Bottom Layer" at 6824.9,2937.62 h60
  text "67 Total" at 5356.16,2813.3 h60
  text ".Layer_Name" at 577,-858.49 h60
M17 Embedded Cavity:
  text ".Layer_Name" at 577,-858.49 h60
M18 Embedded Assembly:
  text ".Layer_Name" at 577,-858.49 h60
M19 Embedded Keepout:
  text ".Layer_Name" at 577,-858.49 h60

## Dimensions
505.85,117.73 to 0,1377.64 on M2 Board Dimensions
0,0 to 0,1377.64 on M2 Board Dimensions
0,-400 to 1000,-400 on M2 Board Dimensions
